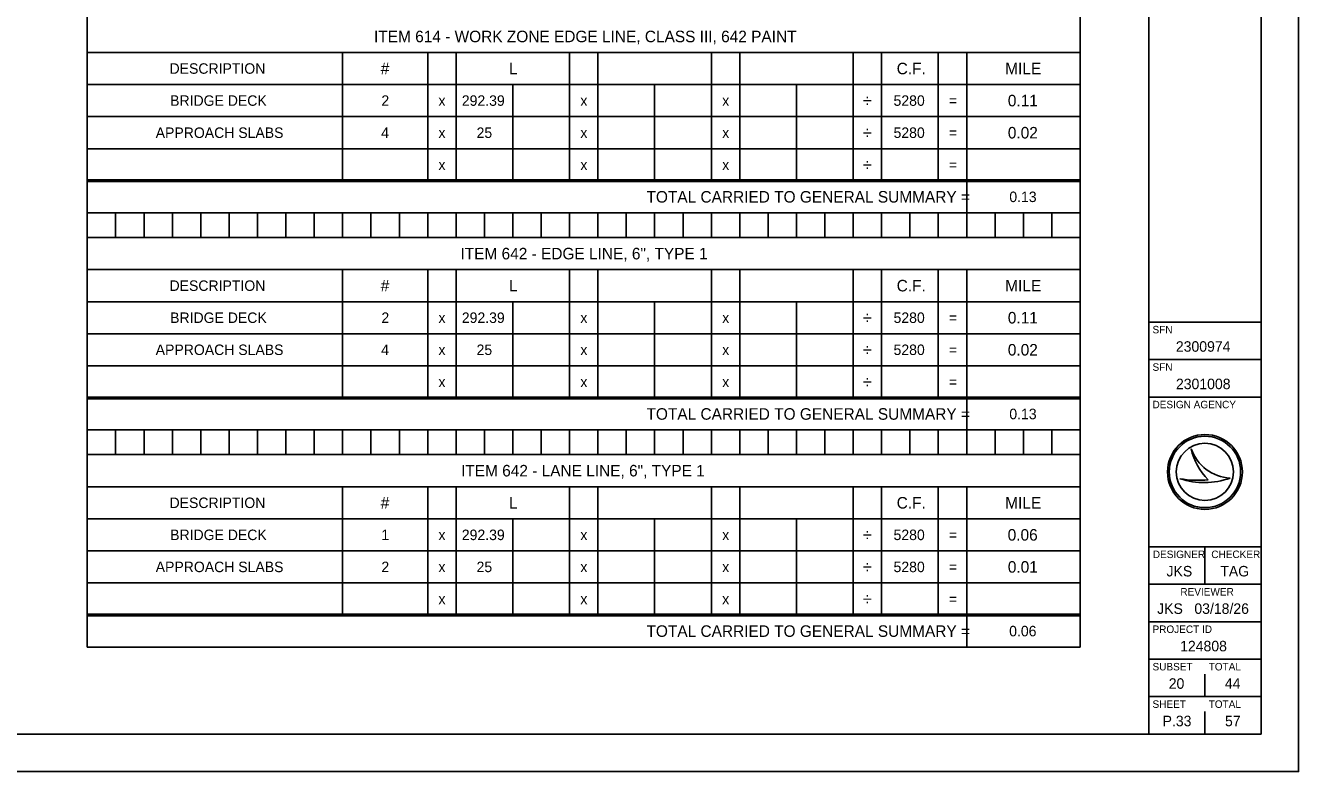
# Model space of a CAD drawing. Extents: x 0 to 34, y 0 to 22.
# Drawn here: x 17 to 34, y 0 to 9.96 of the extents above; entities that cross this region are included whole.
import ezdxf

# ---------------------------------------------------------------- set-up
doc = ezdxf.new("R2010")
doc.units = 0
for name, color, linetype in [('SH_Border', 7, 'Continuous'), ('SH_Cut_Line', 7, 'Continuous'), ('SH_Data', 7, 'Continuous'), ('SH_Text', 7, 'Continuous')]:
    doc.layers.add(name, color=color, linetype=linetype)

msp = doc.modelspace()

# ---------------------------------------------------------------- linework, layer by layer
at = {"layer": 'SH_Border'}
for p, q in [((32, 0.5), (32, 21.5)), ((32, 6), (33.5, 6)), ((32, 5.5), (33.5, 5.5)), ((32, 5), (33.5, 5)), ((32, 3), (33.5, 3)), ((32.75, 3), (32.75, 2.5)), ((32, 2.5), (33.5, 2.5)), ((32, 2), (33.5, 2)), ((32, 1.5), (33.5, 1.5)), ((32, 1), (33.5, 1))]:
    msp.add_line(p, q, dxfattribs=at)
msp.add_lwpolyline([(1.5, 21.5), (33.5, 21.5), (33.5, 0.5), (1.5, 0.5)], close=True, dxfattribs=at)
at = {"layer": 'SH_Cut_Line'}
msp.add_lwpolyline([(0, 0), (34, 0), (34, 22), (0, 22)], close=True, dxfattribs=at)
at = {"layer": 'SH_Data'}
for p, q in [((32.75, 5.675), (32.75, 5.675)), ((32.75, 5.175), (32.75, 5.175)), ((32.567, 4.31), (32.567, 4.31)), ((32.75, 4), (32.75, 4)), ((33.087, 3.919), (33.087, 3.919)), ((32.417, 3.91), (32.417, 3.91)), ((32.75, 1), (32.75, 1.3)), ((32.75, 0.5), (32.75, 0.8)), ((32.375, 0.675), (32.375, 0.675))]:
    msp.add_line(p, q, dxfattribs=at)
for radius in [0.5, 0.477, 0.477, 0.382]:
    msp.add_circle((32.75, 4), radius, dxfattribs=at)
for centre, radius, start, end in [((33.116, 4.498), 0.58, 198.9257, 198.9319), ((33.347, 4.47), 0.796, 191.6379, 191.6421), ((33.116, 4.498), 0.58, 198.9319, 267.1657), ((33.347, 4.47), 0.796, 191.6421, 226.0947), ((32.739, 4.87), 1.013, 251.4576, 290.0832), ((32.648, 5.154), 1.266, 259.4964, 259.4995), ((32.739, 4.87), 1.013, 251.4527, 251.4576), ((32.648, 5.154), 1.266, 259.4995, 276.6672)]:
    msp.add_arc(centre, radius, start, end, dxfattribs=at)
at = {"layer": 'SH_Text'}
for p, q in [((17.826, 10.797), (17.826, 7.876)), ((31.084, 10.797), (31.084, 7.876)), ((17.826, 9.6), (31.084, 9.6)), ((21.235, 9.6), (21.235, 7.898)), ((22.371, 9.6), (22.371, 7.898)), ((22.75, 9.6), (22.75, 7.898)), ((24.266, 9.6), (24.266, 7.898)), ((24.644, 9.6), (24.644, 7.898)), ((26.16, 9.6), (26.16, 7.898)), ((26.538, 9.6), (26.538, 7.898)), ((28.054, 9.6), (28.054, 7.898)), ((28.433, 9.6), (28.433, 7.898)), ((29.19, 9.6), (29.19, 7.898)), ((29.569, 9.6), (29.569, 7.898)), ((17.826, 9.172), (31.084, 9.172)), ((23.508, 9.172), (23.508, 7.898)), ((25.402, 9.172), (25.402, 7.898)), ((27.296, 9.172), (27.296, 7.898)), ((17.826, 8.744), (31.084, 8.744)), ((17.826, 8.315), (31.084, 8.315)), ((17.826, 7.898), (31.084, 7.898)), ((17.826, 7.898), (17.826, 4.977)), ((17.826, 7.876), (31.084, 7.876)), ((29.569, 7.876), (29.569, 7.459)), ((31.084, 7.898), (31.084, 4.977)), ((17.826, 7.459), (31.084, 7.459)), ((17.826, 7.129), (31.084, 7.129)), ((17.826, 6.701), (31.084, 6.701)), ((21.235, 6.701), (21.235, 4.999)), ((22.371, 6.701), (22.371, 4.999)), ((22.75, 6.701), (22.75, 4.999)), ((24.266, 6.701), (24.266, 4.999)), ((24.644, 6.701), (24.644, 4.999)), ((26.16, 6.701), (26.16, 4.999)), ((26.538, 6.701), (26.538, 4.999)), ((28.054, 6.701), (28.054, 4.999)), ((28.433, 6.701), (28.433, 4.999)), ((29.19, 6.701), (29.19, 4.999)), ((29.569, 6.701), (29.569, 4.999)), ((17.826, 6.273), (31.084, 6.273)), ((23.508, 6.273), (23.508, 4.999)), ((25.402, 6.273), (25.402, 4.999)), ((27.296, 6.273), (27.296, 4.999)), ((17.826, 5.845), (31.084, 5.845)), ((17.826, 5.417), (31.084, 5.417)), ((17.826, 4.999), (31.084, 4.999)), ((17.826, 4.999), (17.826, 2.078)), ((17.826, 4.977), (31.084, 4.977)), ((29.569, 4.977), (29.569, 4.56)), ((31.084, 4.999), (31.084, 2.078)), ((17.826, 4.56), (31.084, 4.56)), ((17.826, 4.231), (31.084, 4.231)), ((17.826, 3.802), (31.084, 3.802)), ((21.235, 3.802), (21.235, 2.1)), ((22.371, 3.802), (22.371, 2.1)), ((22.75, 3.802), (22.75, 2.1)), ((24.266, 3.802), (24.266, 2.1)), ((24.644, 3.802), (24.644, 2.1)), ((26.16, 3.802), (26.16, 2.1)), ((26.538, 3.802), (26.538, 2.1)), ((28.054, 3.802), (28.054, 2.1)), ((28.433, 3.802), (28.433, 2.1)), ((29.19, 3.802), (29.19, 2.1)), ((29.569, 3.802), (29.569, 2.1)), ((17.826, 3.374), (31.084, 3.374)), ((23.508, 3.374), (23.508, 2.1)), ((25.402, 3.374), (25.402, 2.1)), ((27.296, 3.374), (27.296, 2.1)), ((17.826, 2.946), (31.084, 2.946)), ((17.826, 2.518), (31.084, 2.518)), ((17.826, 2.1), (31.084, 2.1)), ((17.826, 2.1), (17.826, 1.661)), ((17.826, 2.078), (31.084, 2.078)), ((29.569, 2.078), (29.569, 1.661)), ((31.084, 2.1), (31.084, 1.661)), ((17.826, 1.661), (31.084, 1.661))]:
    msp.add_line(p, q, dxfattribs=at)
for points in [[(17.826, 7.459), (18.204, 7.459), (18.204, 7.129), (17.826, 7.129)], [(18.204, 7.459), (18.583, 7.459), (18.583, 7.129), (18.204, 7.129)], [(18.583, 7.459), (18.962, 7.459), (18.962, 7.129), (18.583, 7.129)], [(18.962, 7.459), (19.341, 7.459), (19.341, 7.129), (18.962, 7.129)], [(19.341, 7.459), (19.72, 7.459), (19.72, 7.129), (19.341, 7.129)], [(19.72, 7.459), (20.098, 7.459), (20.098, 7.129), (19.72, 7.129)], [(20.098, 7.459), (20.477, 7.459), (20.477, 7.129), (20.098, 7.129)], [(20.477, 7.459), (20.856, 7.459), (20.856, 7.129), (20.477, 7.129)], [(20.856, 7.459), (21.235, 7.459), (21.235, 7.129), (20.856, 7.129)], [(21.235, 7.459), (21.614, 7.459), (21.614, 7.129), (21.235, 7.129)], [(21.614, 7.459), (21.993, 7.459), (21.993, 7.129), (21.614, 7.129)], [(21.993, 7.459), (22.371, 7.459), (22.371, 7.129), (21.993, 7.129)], [(22.371, 7.459), (22.75, 7.459), (22.75, 7.129), (22.371, 7.129)], [(22.75, 7.459), (23.129, 7.459), (23.129, 7.129), (22.75, 7.129)], [(23.129, 7.459), (23.508, 7.459), (23.508, 7.129), (23.129, 7.129)], [(23.508, 7.459), (23.887, 7.459), (23.887, 7.129), (23.508, 7.129)], [(23.887, 7.459), (24.266, 7.459), (24.266, 7.129), (23.887, 7.129)], [(24.266, 7.459), (24.644, 7.459), (24.644, 7.129), (24.266, 7.129)], [(24.644, 7.459), (25.023, 7.459), (25.023, 7.129), (24.644, 7.129)], [(25.023, 7.459), (25.402, 7.459), (25.402, 7.129), (25.023, 7.129)], [(25.402, 7.459), (25.781, 7.459), (25.781, 7.129), (25.402, 7.129)], [(25.781, 7.459), (26.16, 7.459), (26.16, 7.129), (25.781, 7.129)], [(26.16, 7.459), (26.538, 7.459), (26.538, 7.129), (26.16, 7.129)], [(26.538, 7.459), (26.917, 7.459), (26.917, 7.129), (26.538, 7.129)], [(26.917, 7.459), (27.296, 7.459), (27.296, 7.129), (26.917, 7.129)], [(27.296, 7.459), (27.675, 7.459), (27.675, 7.129), (27.296, 7.129)], [(27.675, 7.459), (28.054, 7.459), (28.054, 7.129), (27.675, 7.129)], [(28.054, 7.459), (28.433, 7.459), (28.433, 7.129), (28.054, 7.129)], [(28.433, 7.459), (28.811, 7.459), (28.811, 7.129), (28.433, 7.129)], [(28.811, 7.459), (29.19, 7.459), (29.19, 7.129), (28.811, 7.129)], [(29.19, 7.459), (29.569, 7.459), (29.569, 7.129), (29.19, 7.129)], [(29.569, 7.459), (29.948, 7.459), (29.948, 7.129), (29.569, 7.129)], [(29.948, 7.459), (30.327, 7.459), (30.327, 7.129), (29.948, 7.129)], [(30.327, 7.459), (30.706, 7.459), (30.706, 7.129), (30.327, 7.129)], [(30.706, 7.459), (31.084, 7.459), (31.084, 7.129), (30.706, 7.129)], [(17.826, 4.56), (18.204, 4.56), (18.204, 4.231), (17.826, 4.231)], [(18.204, 4.56), (18.583, 4.56), (18.583, 4.231), (18.204, 4.231)], [(18.583, 4.56), (18.962, 4.56), (18.962, 4.231), (18.583, 4.231)], [(18.962, 4.56), (19.341, 4.56), (19.341, 4.231), (18.962, 4.231)], [(19.341, 4.56), (19.72, 4.56), (19.72, 4.231), (19.341, 4.231)], [(19.72, 4.56), (20.098, 4.56), (20.098, 4.231), (19.72, 4.231)], [(20.098, 4.56), (20.477, 4.56), (20.477, 4.231), (20.098, 4.231)], [(20.477, 4.56), (20.856, 4.56), (20.856, 4.231), (20.477, 4.231)], [(20.856, 4.56), (21.235, 4.56), (21.235, 4.231), (20.856, 4.231)], [(21.235, 4.56), (21.614, 4.56), (21.614, 4.231), (21.235, 4.231)], [(21.614, 4.56), (21.993, 4.56), (21.993, 4.231), (21.614, 4.231)], [(21.993, 4.56), (22.371, 4.56), (22.371, 4.231), (21.993, 4.231)], [(22.371, 4.56), (22.75, 4.56), (22.75, 4.231), (22.371, 4.231)], [(22.75, 4.56), (23.129, 4.56), (23.129, 4.231), (22.75, 4.231)], [(23.129, 4.56), (23.508, 4.56), (23.508, 4.231), (23.129, 4.231)], [(23.508, 4.56), (23.887, 4.56), (23.887, 4.231), (23.508, 4.231)], [(23.887, 4.56), (24.266, 4.56), (24.266, 4.231), (23.887, 4.231)], [(24.266, 4.56), (24.644, 4.56), (24.644, 4.231), (24.266, 4.231)], [(24.644, 4.56), (25.023, 4.56), (25.023, 4.231), (24.644, 4.231)], [(25.023, 4.56), (25.402, 4.56), (25.402, 4.231), (25.023, 4.231)], [(25.402, 4.56), (25.781, 4.56), (25.781, 4.231), (25.402, 4.231)], [(25.781, 4.56), (26.16, 4.56), (26.16, 4.231), (25.781, 4.231)], [(26.16, 4.56), (26.538, 4.56), (26.538, 4.231), (26.16, 4.231)], [(26.538, 4.56), (26.917, 4.56), (26.917, 4.231), (26.538, 4.231)], [(26.917, 4.56), (27.296, 4.56), (27.296, 4.231), (26.917, 4.231)], [(27.296, 4.56), (27.675, 4.56), (27.675, 4.231), (27.296, 4.231)], [(27.675, 4.56), (28.054, 4.56), (28.054, 4.231), (27.675, 4.231)], [(28.054, 4.56), (28.433, 4.56), (28.433, 4.231), (28.054, 4.231)], [(28.433, 4.56), (28.811, 4.56), (28.811, 4.231), (28.433, 4.231)], [(28.811, 4.56), (29.19, 4.56), (29.19, 4.231), (28.811, 4.231)], [(29.19, 4.56), (29.569, 4.56), (29.569, 4.231), (29.19, 4.231)], [(29.569, 4.56), (29.948, 4.56), (29.948, 4.231), (29.569, 4.231)], [(29.948, 4.56), (30.327, 4.56), (30.327, 4.231), (29.948, 4.231)], [(30.327, 4.56), (30.706, 4.56), (30.706, 4.231), (30.327, 4.231)], [(30.706, 4.56), (31.084, 4.56), (31.084, 4.231), (30.706, 4.231)]]:
    msp.add_lwpolyline(points, close=True, dxfattribs=at)

# ---------------------------------------------------------------- texts
at = {"layer": 'SH_Data'}
for s, height, p in [('SFN', 0.1, (32.05, 5.85)), ('2300974', 0.14, (32.362, 5.605)), ('SFN', 0.1, (32.05, 5.35)), ('2301008', 0.14, (32.363, 5.105)), ('DESIGN AGENCY', 0.1, (32.05, 4.85)), ('DESIGNER', 0.1, (32.054, 2.85)), ('CHECKER', 0.1, (32.835, 2.85)), ('JKS', 0.14, (32.237, 2.605)), ('TAG', 0.14, (32.955, 2.605)), ('REVIEWER', 0.1, (32.422, 2.35)), ('JKS', 0.14, (32.112, 2.105)), ('03/18/26', 0.14, (32.609, 2.105)), ('PROJECT ID', 0.1, (32.05, 1.85)), ('124808', 0.14, (32.419, 1.605)), ('SUBSET', 0.1, (32.05, 1.35)), ('TOTAL', 0.1, (32.8, 1.35)), ('20', 0.14, (32.267, 1.105)), ('44', 0.14, (33.016, 1.105)), ('SHEET', 0.1, (32.05, 0.85)), ('TOTAL', 0.1, (32.8, 0.85)), ('P.33', 0.14, (32.185, 0.605)), ('57', 0.14, (33.018, 0.605))]:
    msp.add_text(s, height=height, dxfattribs=at).set_placement(p)
at = {"layer": 'SH_Text'}
for s, height, p in [('ITEM 614 - WORK ZONE EDGE LINE, CLASS III, 642 PAINT', 0.154, (21.655, 9.737)), ('DESCRIPTION', 0.14, (18.924, 9.316)), ('#', 0.154, (21.744, 9.309)), ('L', 0.154, (23.457, 9.309)), ('C.F.', 0.154, (28.634, 9.309)), ('MILE', 0.154, (30.083, 9.309)), ('BRIDGE DECK', 0.14, (18.932, 8.888)), ('2', 0.14, (21.753, 8.888)), ('292.39', 0.14, (22.827, 8.888)), ('5280', 0.14, (28.592, 8.888)), ('0.11', 0.154, (30.118, 8.881)), ('x', 0.14, (22.515, 8.888)), ('x', 0.14, (24.41, 8.888)), ('x', 0.14, (26.304, 8.888)), ('÷', 0.168, (28.181, 8.874)), ('=', 0.14, (29.33, 8.888)), ('APPROACH SLABS', 0.14, (18.739, 8.459)), ('4', 0.14, (21.75, 8.459)), ('x', 0.14, (22.515, 8.459)), ('25', 0.14, (23.024, 8.459)), ('x', 0.14, (24.41, 8.459)), ('x', 0.14, (26.304, 8.459)), ('÷', 0.168, (28.181, 8.445)), ('5280', 0.14, (28.592, 8.459)), ('=', 0.14, (29.33, 8.459)), ('0.02', 0.154, (30.118, 8.452)), ('x', 0.14, (22.515, 8.031)), ('x', 0.14, (24.41, 8.031)), ('x', 0.14, (26.304, 8.031)), ('÷', 0.168, (28.181, 8.017)), ('=', 0.14, (29.33, 8.031)), ('TOTAL CARRIED TO GENERAL SUMMARY =', 0.154, (25.293, 7.596)), ('0.13', 0.14, (30.138, 7.603)), ('ITEM 642 - EDGE LINE, 6", TYPE 1', 0.154, (22.809, 6.838)), ('DESCRIPTION', 0.14, (18.924, 6.417)), ('#', 0.154, (21.744, 6.41)), ('L', 0.154, (23.457, 6.41)), ('C.F.', 0.154, (28.634, 6.41)), ('MILE', 0.154, (30.083, 6.41)), ('BRIDGE DECK', 0.14, (18.932, 5.989)), ('2', 0.14, (21.753, 5.989)), ('292.39', 0.14, (22.827, 5.989)), ('5280', 0.14, (28.592, 5.989)), ('0.11', 0.154, (30.118, 5.982)), ('x', 0.14, (22.515, 5.989)), ('x', 0.14, (24.41, 5.989)), ('x', 0.14, (26.304, 5.989)), ('÷', 0.168, (28.181, 5.975)), ('=', 0.14, (29.33, 5.989)), ('APPROACH SLABS', 0.14, (18.739, 5.561)), ('4', 0.14, (21.75, 5.561)), ('x', 0.14, (22.515, 5.561)), ('25', 0.14, (23.024, 5.561)), ('x', 0.14, (24.41, 5.561)), ('x', 0.14, (26.304, 5.561)), ('÷', 0.168, (28.181, 5.547)), ('5280', 0.14, (28.592, 5.561)), ('=', 0.14, (29.33, 5.561)), ('0.02', 0.154, (30.118, 5.554)), ('x', 0.14, (22.515, 5.132)), ('x', 0.14, (24.41, 5.132)), ('x', 0.14, (26.304, 5.132)), ('÷', 0.168, (28.181, 5.118)), ('=', 0.14, (29.33, 5.132)), ('TOTAL CARRIED TO GENERAL SUMMARY =', 0.154, (25.293, 4.697)), ('0.13', 0.14, (30.138, 4.704)), ('ITEM 642 - LANE LINE, 6", TYPE 1', 0.154, (22.817, 3.94)), ('DESCRIPTION', 0.14, (18.924, 3.518)), ('#', 0.154, (21.744, 3.511)), ('L', 0.154, (23.457, 3.511)), ('C.F.', 0.154, (28.634, 3.511)), ('MILE', 0.154, (30.083, 3.511)), ('BRIDGE DECK', 0.14, (18.932, 3.09)), ('1', 0.14, (21.753, 3.09)), ('292.39', 0.14, (22.827, 3.09)), ('5280', 0.14, (28.592, 3.09)), ('0.06', 0.154, (30.116, 3.083)), ('x', 0.14, (22.515, 3.09)), ('x', 0.14, (24.41, 3.09)), ('x', 0.14, (26.304, 3.09)), ('÷', 0.168, (28.181, 3.076)), ('=', 0.14, (29.33, 3.09)), ('APPROACH SLABS', 0.14, (18.739, 2.662)), ('2', 0.14, (21.753, 2.662)), ('x', 0.14, (22.515, 2.662)), ('25', 0.14, (23.024, 2.662)), ('x', 0.14, (24.41, 2.662)), ('x', 0.14, (26.304, 2.662)), ('÷', 0.168, (28.181, 2.648)), ('5280', 0.14, (28.592, 2.662)), ('=', 0.14, (29.33, 2.662)), ('0.01', 0.154, (30.118, 2.655)), ('x', 0.14, (22.515, 2.234)), ('x', 0.14, (24.41, 2.234)), ('x', 0.14, (26.304, 2.234)), ('÷', 0.168, (28.181, 2.22)), ('=', 0.14, (29.33, 2.234)), ('TOTAL CARRIED TO GENERAL SUMMARY =', 0.154, (25.293, 1.798)), ('0.06', 0.14, (30.136, 1.805))]:
    msp.add_text(s, height=height, dxfattribs=at).set_placement(p)

doc.saveas('drawing.dxf')
